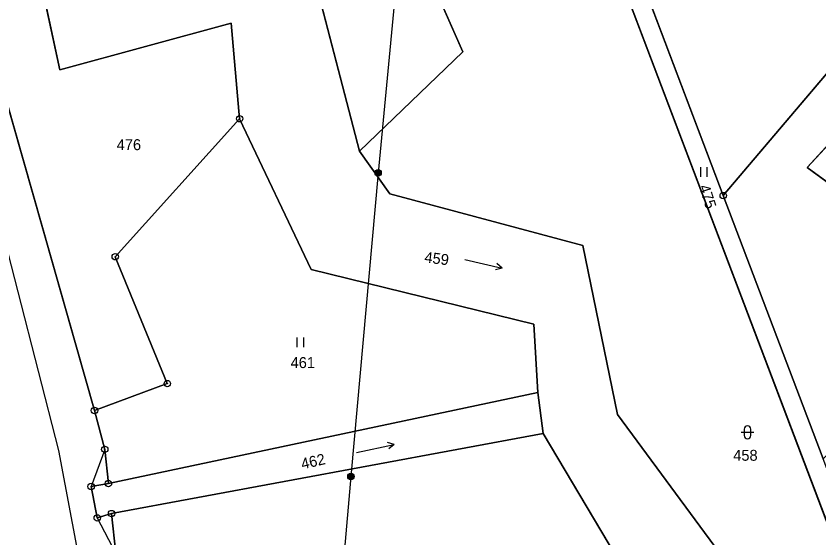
# Model space of a CAD drawing. Extents: x -689422 to -685210, y -987725 to -982160.
# Drawn here: x -686678.2 to -686553.1, y -986321.6 to -986240.3 of the extents above; entities that cross this region are included whole.
import ezdxf

# ---------------------------------------------------------------- set-up
doc = ezdxf.new("R2010")
doc.units = 0
for name, color, linetype in [('KN_Hranice_katastrální území', 7, 'Continuous'), ('KN_Hranice_parcel', 7, 'Continuous'), ('KN_Hranice_parcel_vnitrni_kresba', 7, 'Continuous'), ('KN_Parcelni cisla', 7, 'Continuous'), ('KN_Polygon parcely', 7, 'Continuous'), ('KN_Pozemkove predmety', 7, 'Continuous'), ('KN_POZEMKY_OSTATNI PLOCHA', 7, 'Continuous'), ('KN_POZEMKY_TTP', 7, 'Continuous'), ('KN_POZEMKY_VODNI_PLOCHA', 7, 'Continuous'), ('KN_POZEMKY_ZAHRADA', 7, 'Continuous'), ('KN_POZEMKY_ZASTAVENA PLOCHA', 7, 'Continuous'), ('KN_VYUZITI_07_vodni plocha_tok prirozeny', 7, 'Continuous'), ('KN_VYUZITI_08_vodni plocha _tok umely', 7, 'Continuous'), ('KN_VYUZITI_16_ostatni plocha_silnice', 7, 'Continuous'), ('KN_VYUZITI_23_ostatni plocha_manipulacni plocha', 7, 'Continuous'), ('KN_VYUZITI_27_ostatni plocha_neplodna puda', 7, 'Continuous'), ('KN_Značky bodu BP', 7, 'Continuous'), ('KN_Značky kultur', 7, 'Continuous')]:
    doc.layers.add(name, color=color, linetype=linetype)

msp = doc.modelspace()

# ---------------------------------------------------------------- linework, layer by layer
at = {"layer": 'KN_Hranice_katastrální území'}
for points in [[(-686689.98, -986217.58), (-686665.99, -986301.77), (-686664.4, -986307.82), (-686663.83, -986313.14), (-686666.51, -986313.61), (-686665.56, -986318.5), (-686663.33, -986317.82), (-686662.66, -986324.04), (-686657.08, -986369.79), (-686655.33, -986417.82), (-686658.73, -986468.88), (-686659.13, -986474.94), (-686667.92, -986522.94), (-686676.51, -986555.42)], [(-686676.51, -986555.42), (-686667.92, -986522.94), (-686659.13, -986474.94), (-686658.73, -986468.88), (-686655.33, -986417.82), (-686657.08, -986369.79), (-686662.66, -986324.04), (-686663.33, -986317.82), (-686665.56, -986318.5), (-686666.51, -986313.61), (-686663.83, -986313.14), (-686664.4, -986307.82), (-686665.99, -986301.77), (-686689.98, -986217.58)]]:
    msp.add_lwpolyline(points, dxfattribs=at)
at = {"layer": 'KN_Hranice_parcel'}
for p, q in [((-686665.99, -986301.77), (-686689.98, -986217.58)), ((-686665.99, -986301.77), (-686689.98, -986217.58)), ((-686546.45, -986333.52), (-686590.46, -986217.47)), ((-686568.04, -986268.3), (-686544.95, -986241.07)), ((-686552.49, -986309.3), (-686568.04, -986268.3)), ((-686663.83, -986313.14), (-686596.93, -986298.95)), ((-686596.93, -986298.95), (-686596.08, -986305.34)), ((-686596.08, -986305.34), (-686663.33, -986317.82)), ((-686662.66, -986324.04), (-686663.33, -986317.82)), ((-686662.66, -986324.04), (-686663.33, -986317.82))]:
    msp.add_line(p, q, dxfattribs=at)
for points in [[(-686624.7, -986261.38), (-686608.6, -986245.91), (-686616.61, -986227.78), (-686637.91, -986202.22), (-686653.2, -986182.49), (-686653.43, -986174.36)], [(-686624.7, -986261.38), (-686636.01, -986217.82), (-686664.66, -986238.46), (-686663.73, -986216.26), (-686671.51, -986201.06), (-686703.45, -986202.79)], [(-686679.56, -986210.72), (-686671.4, -986248.73), (-686644.68, -986241.46), (-686643.38, -986256.33)], [(-686568.04, -986268.3), (-686585.99, -986220.97), (-686590.46, -986217.47)], [(-686539.46, -986246.23), (-686540.75, -986247.75), (-686548.62, -986257.03), (-686554.96, -986263.93), (-686536.15, -986277.69), (-686533.05, -986273.89), (-686523.37, -986262.39), (-686522.73, -986261.63)], [(-686665.99, -986301.77), (-686654.65, -986297.58), (-686662.76, -986277.82), (-686643.38, -986256.33)], [(-686643.38, -986256.33), (-686632.23, -986279.81), (-686597.54, -986288.3), (-686596.93, -986298.95)], [(-686537.43, -986399.99), (-686549.98, -986397.14), (-686553.27, -986362.5), (-686568.63, -986323.94), (-686584.5, -986302.4), (-686589.89, -986276.07), (-686619.99, -986268), (-686624.7, -986261.38)], [(-686663.83, -986313.14), (-686664.4, -986307.82), (-686665.99, -986301.77)], [(-686663.83, -986313.14), (-686664.4, -986307.82), (-686665.99, -986301.77)], [(-686596.08, -986305.34), (-686570.29, -986348.74), (-686562.52, -986391.3), (-686560.8, -986399.5), (-686557.38, -986401.84)], [(-686663.33, -986317.82), (-686665.56, -986318.5), (-686666.51, -986313.61), (-686663.83, -986313.14)], [(-686663.33, -986317.82), (-686665.56, -986318.5), (-686666.51, -986313.61), (-686663.83, -986313.14)]]:
    msp.add_lwpolyline(points, dxfattribs=at)
at = {"layer": 'KN_Hranice_parcel_vnitrni_kresba'}
for p, q in [((-686681.82, -986268.28), (-686671.61, -986308.01)), ((-686671.61, -986308.01), (-686667.82, -986328.22)), ((-686664.4, -986307.82), (-686666.51, -986313.61)), ((-686665.56, -986318.5), (-686662.66, -986324.04))]:
    msp.add_line(p, q, dxfattribs=at)
at = {"layer": 'KN_Polygon parcely'}
for points in [[(-686544.95, -986241.07), (-686563.88, -986223.26), (-686589.76, -986201.48), (-686591, -986202.9), (-686590.46, -986217.47), (-686585.99, -986220.97), (-686568.04, -986268.3)], [(-686689.98, -986217.58), (-686665.99, -986301.77), (-686654.65, -986297.58), (-686662.76, -986277.82), (-686643.38, -986256.33), (-686644.68, -986241.46), (-686671.4, -986248.73), (-686679.56, -986210.72), (-686696.47, -986210.62), (-686693.87, -986213.32)], [(-686585.99, -986220.97), (-686590.46, -986217.47), (-686546.45, -986333.52), (-686543.91, -986331.92), (-686552.49, -986309.3), (-686568.04, -986268.3)], [(-686512.36, -986270.37), (-686522.73, -986261.63), (-686523.37, -986262.39), (-686533.05, -986273.89), (-686536.15, -986277.69), (-686554.96, -986263.93), (-686548.62, -986257.03), (-686540.75, -986247.75), (-686539.46, -986246.23), (-686544.95, -986241.07), (-686568.04, -986268.3), (-686552.49, -986309.3)], [(-686554.96, -986263.93), (-686536.15, -986277.69), (-686533.05, -986273.89), (-686523.37, -986262.39), (-686522.73, -986261.63), (-686522.08, -986260.86), (-686539.46, -986246.23), (-686540.75, -986247.75), (-686548.62, -986257.03)], [(-686664.4, -986307.82), (-686663.83, -986313.14), (-686596.93, -986298.95), (-686597.54, -986288.3), (-686632.23, -986279.81), (-686643.38, -986256.33), (-686662.76, -986277.82), (-686654.65, -986297.58), (-686665.99, -986301.77)], [(-686665.56, -986318.5), (-686663.33, -986317.82), (-686596.08, -986305.34), (-686596.93, -986298.95), (-686663.83, -986313.14), (-686666.51, -986313.61)], [(-686663.33, -986317.82), (-686662.66, -986324.04), (-686657.55, -986340.41), (-686649.56, -986342.47), (-686644.48, -986360.93), (-686626.84, -986358.25), (-686633.76, -986385.2), (-686640.61, -986413.7), (-686639.8, -986420.06), (-686557.38, -986401.84), (-686560.8, -986399.5), (-686562.52, -986391.3), (-686570.29, -986348.74), (-686596.08, -986305.34)]]:
    msp.add_lwpolyline(points, close=True, dxfattribs=at)
for points in [[(-686679.56, -986210.72), (-686671.4, -986248.73), (-686644.68, -986241.46), (-686643.38, -986256.33), (-686632.23, -986279.81), (-686597.54, -986288.3), (-686596.93, -986298.95), (-686596.08, -986305.34), (-686570.29, -986348.74), (-686562.52, -986391.3), (-686560.8, -986399.5), (-686557.38, -986401.84), (-686553.34, -986411.64), (-686558.79, -986434.27), (-686537.77, -986479.73), (-686538.67, -986550.05)], [(-686676.51, -986555.42), (-686667.92, -986522.94), (-686659.13, -986474.94), (-686658.73, -986468.88), (-686655.33, -986417.82), (-686657.08, -986369.79), (-686662.66, -986324.04), (-686663.33, -986317.82), (-686665.56, -986318.5), (-686666.51, -986313.61), (-686663.83, -986313.14), (-686664.4, -986307.82), (-686665.99, -986301.77), (-686689.98, -986217.58)], [(-686616.61, -986227.78), (-686608.6, -986245.91), (-686624.7, -986261.38), (-686619.99, -986268), (-686589.89, -986276.07), (-686584.5, -986302.4), (-686568.63, -986323.94), (-686553.27, -986362.5), (-686549.98, -986397.14), (-686537.43, -986399.99), (-686528.35, -986396.6), (-686530.52, -986394.23), (-686533.26, -986378.29), (-686534.02, -986370.05), (-686537.74, -986359.11), (-686541.91, -986346.87), (-686546.45, -986333.52), (-686590.46, -986217.47)], [(-686636.01, -986217.82), (-686624.7, -986261.38), (-686608.6, -986245.91), (-686616.61, -986227.78)], [(-686529.76, -986542.24), (-686530.23, -986465.49), (-686547.77, -986439.87), (-686534.21, -986418.86), (-686537.43, -986399.99), (-686549.98, -986397.14), (-686553.27, -986362.5), (-686568.63, -986323.94), (-686584.5, -986302.4), (-686589.89, -986276.07), (-686619.99, -986268), (-686624.7, -986261.38), (-686636.01, -986217.82)]]:
    msp.add_lwpolyline(points, dxfattribs=at)
at = {"layer": 'KN_Pozemkove predmety'}
for p, q in [((-686614.02, -986183.36), (-686621.81, -986264.75)), ((-686621.81, -986264.75), (-686626.05, -986312.04)), ((-686626.05, -986312.04), (-686630.6, -986362.78))]:
    msp.add_line(p, q, dxfattribs=at)
for centre, radius in [((-686621.81, -986264.75), 0.5), ((-686621.81, -986264.75), 0.4), ((-686621.81, -986264.75), 0.3), ((-686621.81, -986264.75), 0.2), ((-686621.81, -986264.75), 0.1), ((-686626.05, -986312.04), 0.5), ((-686626.05, -986312.04), 0.4), ((-686626.05, -986312.04), 0.3), ((-686626.05, -986312.04), 0.2), ((-686626.05, -986312.04), 0.1)]:
    msp.add_circle(centre, radius, dxfattribs=at)
at = {"layer": 'KN_POZEMKY_OSTATNI PLOCHA'}
for p, q in [((-686679.56, -986210.72), (-686671.4, -986248.73)), ((-686689.98, -986217.58), (-686665.99, -986301.77)), ((-686665.99, -986301.77), (-686689.98, -986217.58)), ((-686590.46, -986217.47), (-686546.45, -986333.52)), ((-686624.7, -986261.38), (-686636.01, -986217.82)), ((-686608.6, -986245.91), (-686616.61, -986227.78)), ((-686616.61, -986227.78), (-686608.6, -986245.91)), ((-686671.4, -986248.73), (-686644.68, -986241.46)), ((-686644.68, -986241.46), (-686643.38, -986256.33)), ((-686624.7, -986261.38), (-686608.6, -986245.91)), ((-686608.6, -986245.91), (-686624.7, -986261.38)), ((-686643.38, -986256.33), (-686662.76, -986277.82)), ((-686619.99, -986268), (-686624.7, -986261.38)), ((-686589.89, -986276.07), (-686619.99, -986268)), ((-686584.5, -986302.4), (-686589.89, -986276.07)), ((-686662.76, -986277.82), (-686654.65, -986297.58)), ((-686654.65, -986297.58), (-686665.99, -986301.77)), ((-686665.99, -986301.77), (-686664.4, -986307.82)), ((-686568.63, -986323.94), (-686584.5, -986302.4)), ((-686664.4, -986307.82), (-686663.83, -986313.14)), ((-686663.83, -986313.14), (-686666.51, -986313.61)), ((-686666.51, -986313.61), (-686665.56, -986318.5)), ((-686665.56, -986318.5), (-686663.33, -986317.82)), ((-686663.33, -986317.82), (-686662.66, -986324.04))]:
    msp.add_line(p, q, dxfattribs=at)
at = {"layer": 'KN_POZEMKY_TTP'}
for p, q in [((-686546.45, -986333.52), (-686590.46, -986217.47)), ((-686585.99, -986220.97), (-686568.04, -986268.3)), ((-686662.76, -986277.82), (-686643.38, -986256.33)), ((-686643.38, -986256.33), (-686632.23, -986279.81)), ((-686568.04, -986268.3), (-686552.49, -986309.3)), ((-686654.65, -986297.58), (-686662.76, -986277.82)), ((-686632.23, -986279.81), (-686597.54, -986288.3)), ((-686597.54, -986288.3), (-686596.93, -986298.95)), ((-686665.99, -986301.77), (-686654.65, -986297.58)), ((-686596.93, -986298.95), (-686663.83, -986313.14)), ((-686664.4, -986307.82), (-686665.99, -986301.77)), ((-686663.33, -986317.82), (-686596.08, -986305.34)), ((-686596.08, -986305.34), (-686570.29, -986348.74)), ((-686663.83, -986313.14), (-686664.4, -986307.82)), ((-686662.66, -986324.04), (-686663.33, -986317.82))]:
    msp.add_line(p, q, dxfattribs=at)
at = {"layer": 'KN_POZEMKY_VODNI_PLOCHA'}
for p, q in [((-686671.4, -986248.73), (-686679.56, -986210.72)), ((-686636.01, -986217.82), (-686624.7, -986261.38)), ((-686644.68, -986241.46), (-686671.4, -986248.73)), ((-686643.38, -986256.33), (-686644.68, -986241.46)), ((-686632.23, -986279.81), (-686643.38, -986256.33)), ((-686624.7, -986261.38), (-686619.99, -986268)), ((-686619.99, -986268), (-686589.89, -986276.07)), ((-686589.89, -986276.07), (-686584.5, -986302.4)), ((-686597.54, -986288.3), (-686632.23, -986279.81)), ((-686596.93, -986298.95), (-686597.54, -986288.3)), ((-686663.83, -986313.14), (-686596.93, -986298.95)), ((-686596.08, -986305.34), (-686596.93, -986298.95)), ((-686596.93, -986298.95), (-686596.08, -986305.34)), ((-686584.5, -986302.4), (-686568.63, -986323.94)), ((-686596.08, -986305.34), (-686663.33, -986317.82)), ((-686570.29, -986348.74), (-686596.08, -986305.34)), ((-686666.51, -986313.61), (-686663.83, -986313.14)), ((-686665.56, -986318.5), (-686666.51, -986313.61)), ((-686663.33, -986317.82), (-686665.56, -986318.5))]:
    msp.add_line(p, q, dxfattribs=at)
at = {"layer": 'KN_POZEMKY_ZAHRADA'}
for p, q in [((-686568.04, -986268.3), (-686585.99, -986220.97)), ((-686568.04, -986268.3), (-686544.95, -986241.07)), ((-686544.95, -986241.07), (-686568.04, -986268.3)), ((-686548.62, -986257.03), (-686554.96, -986263.93)), ((-686554.96, -986263.93), (-686536.15, -986277.69)), ((-686552.49, -986309.3), (-686568.04, -986268.3))]:
    msp.add_line(p, q, dxfattribs=at)
at = {"layer": 'KN_POZEMKY_ZASTAVENA PLOCHA'}
for p, q in [((-686554.96, -986263.93), (-686548.62, -986257.03)), ((-686536.15, -986277.69), (-686554.96, -986263.93))]:
    msp.add_line(p, q, dxfattribs=at)
at = {"layer": 'KN_VYUZITI_07_vodni plocha_tok prirozeny'}
for p, q in [((-686671.4, -986248.73), (-686679.56, -986210.72)), ((-686636.01, -986217.82), (-686624.7, -986261.38)), ((-686644.68, -986241.46), (-686671.4, -986248.73)), ((-686643.38, -986256.33), (-686644.68, -986241.46)), ((-686632.23, -986279.81), (-686643.38, -986256.33)), ((-686624.7, -986261.38), (-686619.99, -986268)), ((-686619.99, -986268), (-686589.89, -986276.07)), ((-686589.89, -986276.07), (-686584.5, -986302.4)), ((-686597.54, -986288.3), (-686632.23, -986279.81)), ((-686596.93, -986298.95), (-686597.54, -986288.3)), ((-686596.08, -986305.34), (-686596.93, -986298.95)), ((-686584.5, -986302.4), (-686568.63, -986323.94)), ((-686570.29, -986348.74), (-686596.08, -986305.34))]:
    msp.add_line(p, q, dxfattribs=at)
at = {"layer": 'KN_VYUZITI_08_vodni plocha _tok umely'}
for p, q in [((-686663.83, -986313.14), (-686596.93, -986298.95)), ((-686596.93, -986298.95), (-686596.08, -986305.34)), ((-686596.08, -986305.34), (-686663.33, -986317.82)), ((-686666.51, -986313.61), (-686663.83, -986313.14)), ((-686665.56, -986318.5), (-686666.51, -986313.61)), ((-686663.33, -986317.82), (-686665.56, -986318.5))]:
    msp.add_line(p, q, dxfattribs=at)
at = {"layer": 'KN_VYUZITI_16_ostatni plocha_silnice'}
for p, q in [((-686689.98, -986217.58), (-686665.99, -986301.77)), ((-686665.99, -986301.77), (-686664.4, -986307.82)), ((-686664.4, -986307.82), (-686663.83, -986313.14)), ((-686663.83, -986313.14), (-686666.51, -986313.61)), ((-686666.51, -986313.61), (-686665.56, -986318.5)), ((-686665.56, -986318.5), (-686663.33, -986317.82)), ((-686663.33, -986317.82), (-686662.66, -986324.04))]:
    msp.add_line(p, q, dxfattribs=at)
at = {"layer": 'KN_VYUZITI_23_ostatni plocha_manipulacni plocha'}
for p, q in [((-686679.56, -986210.72), (-686671.4, -986248.73)), ((-686665.99, -986301.77), (-686689.98, -986217.58)), ((-686624.7, -986261.38), (-686636.01, -986217.82)), ((-686616.61, -986227.78), (-686608.6, -986245.91)), ((-686671.4, -986248.73), (-686644.68, -986241.46)), ((-686644.68, -986241.46), (-686643.38, -986256.33)), ((-686608.6, -986245.91), (-686624.7, -986261.38)), ((-686643.38, -986256.33), (-686662.76, -986277.82)), ((-686662.76, -986277.82), (-686654.65, -986297.58)), ((-686654.65, -986297.58), (-686665.99, -986301.77))]:
    msp.add_line(p, q, dxfattribs=at)
at = {"layer": 'KN_VYUZITI_27_ostatni plocha_neplodna puda'}
for p, q in [((-686590.46, -986217.47), (-686546.45, -986333.52)), ((-686608.6, -986245.91), (-686616.61, -986227.78)), ((-686624.7, -986261.38), (-686608.6, -986245.91)), ((-686619.99, -986268), (-686624.7, -986261.38)), ((-686589.89, -986276.07), (-686619.99, -986268)), ((-686584.5, -986302.4), (-686589.89, -986276.07)), ((-686568.63, -986323.94), (-686584.5, -986302.4))]:
    msp.add_line(p, q, dxfattribs=at)
at = {"layer": 'KN_Značky bodu BP'}
for centre, radius in [((-686643.38, -986256.33), 0.5), ((-686643.38, -986256.33), 0.0303), ((-686568.04, -986268.3), 0.5), ((-686568.04, -986268.3), 0.0303), ((-686662.76, -986277.82), 0.5), ((-686662.76, -986277.82), 0.0303), ((-686654.65, -986297.58), 0.5), ((-686654.65, -986297.58), 0.0303), ((-686665.99, -986301.77), 0.5), ((-686665.99, -986301.77), 0.5), ((-686665.99, -986301.77), 0.0303), ((-686665.99, -986301.77), 0.0303), ((-686664.4, -986307.82), 0.5), ((-686664.4, -986307.82), 0.5), ((-686664.4, -986307.82), 0.0303), ((-686664.4, -986307.82), 0.0303), ((-686663.83, -986313.14), 0.5), ((-686663.83, -986313.14), 0.5), ((-686666.51, -986313.61), 0.5), ((-686666.51, -986313.61), 0.5), ((-686666.51, -986313.61), 0.0303), ((-686666.51, -986313.61), 0.0303), ((-686663.83, -986313.14), 0.0303), ((-686663.83, -986313.14), 0.0303), ((-686663.33, -986317.82), 0.5), ((-686663.33, -986317.82), 0.5), ((-686665.56, -986318.5), 0.5), ((-686665.56, -986318.5), 0.5), ((-686665.56, -986318.5), 0.0303), ((-686665.56, -986318.5), 0.0303), ((-686663.33, -986317.82), 0.0303), ((-686663.33, -986317.82), 0.0303)]:
    msp.add_circle(centre, radius, dxfattribs=at)
at = {"layer": 'KN_Značky kultur'}
for p, q in [((-686571.55, -986265.38), (-686571.55, -986263.88)), ((-686570.55, -986265.38), (-686570.55, -986263.88)), ((-686608.31, -986278.26), (-686602.46, -986279.61)), ((-686602.46, -986279.61), (-686603.3, -986278.9)), ((-686602.46, -986279.61), (-686603.53, -986279.88)), ((-686634.4, -986291.91), (-686634.4, -986290.41)), ((-686633.4, -986291.91), (-686633.4, -986290.41)), ((-686565.26, -986305.17), (-686563.26, -986305.17)), ((-686564.76, -986304.67), (-686564.76, -986305.67)), ((-686563.76, -986305.67), (-686563.76, -986304.67)), ((-686625.16, -986308.29), (-686619.29, -986307.04)), ((-686619.29, -986307.04), (-686620.35, -986306.75)), ((-686619.29, -986307.04), (-686620.14, -986307.73))]:
    msp.add_line(p, q, dxfattribs=at)
for centre, start, end in [((-686564.26, -986304.67), 0, 180), ((-686564.26, -986305.67), 180, 359.9879)]:
    msp.add_arc(centre, 0.5, start, end, dxfattribs=at)

# ---------------------------------------------------------------- texts
at = {"layer": 'KN_Parcelni cisla'}
for s, p in [('476', (-686662.53, -986261.22)), ('461', (-686635.44, -986295.16)), ('458', (-686566.48, -986309.6))]:
    msp.add_text(s, height=1.7, dxfattribs=at).set_placement(p)
for s, rotation, p in [('475', 288, (-686571.85, -986266.9)), ('459', 353, (-686614.66, -986278.7)), ('462', 13, (-686633.6, -986310.95))]:
    msp.add_text(s, height=1.7, rotation=rotation, dxfattribs=at).set_placement(p)

doc.saveas('drawing.dxf')
